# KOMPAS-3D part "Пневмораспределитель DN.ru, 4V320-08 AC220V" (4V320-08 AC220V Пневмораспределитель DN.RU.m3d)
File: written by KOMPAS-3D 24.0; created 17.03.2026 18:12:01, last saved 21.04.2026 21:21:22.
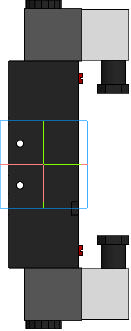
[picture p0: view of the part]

Document properties: Автор: R2D2; Полное имя файла: 4V320-08 AC220V Пневмораспредели тель DN.ru.cdw

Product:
- Part/product: Пневмораспределитель DN.ru  | designation 4V320-08 AC220V
    Масса: 1.2
    Раздел спецификации: Прочие изделия
    Форматы листов документа: A3
    Примечание: D290-00334

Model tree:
1. Операция без истории:1

Expressions: 4V320-08 AC220V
